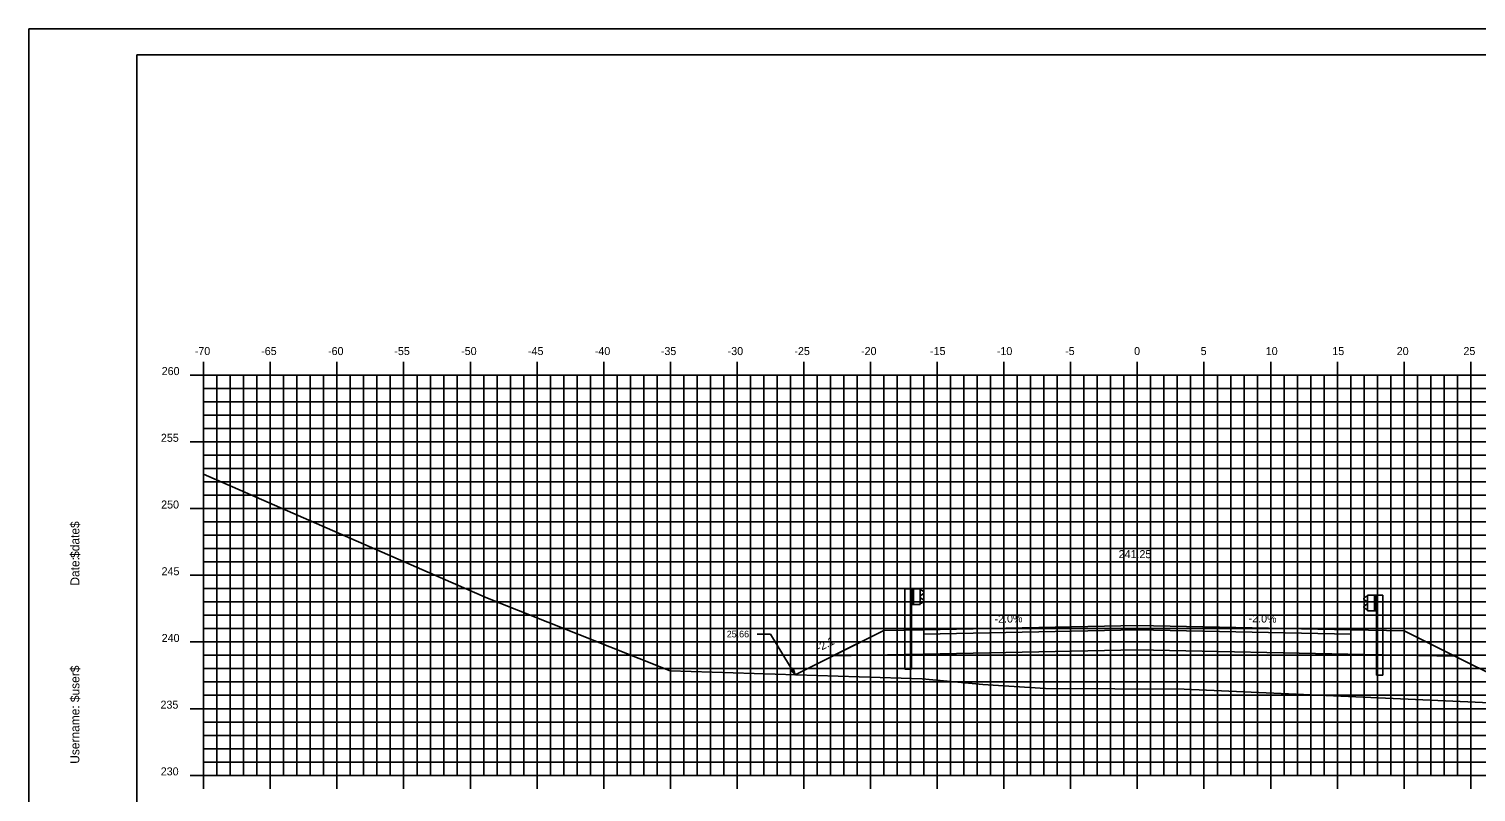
# Model space of a CAD drawing. Extents: x 1160718 to 1173142, y 616002 to 617630.
# Drawn here: x 1169435.8 to 1169544.3, y 616666.7 to 616723.9 of the extents above; entities that cross this region are included whole.
import ezdxf

# ---------------------------------------------------------------- set-up
doc = ezdxf.new("R2010")
doc.units = 0
for name, color, linetype in [('ANNOTATION', 7, 'Continuous'), ('BORDER', 7, 'Continuous'), ('D_Guardrail_Beam_Lt', 7, 'Continuous'), ('D_Guardrail_Beam_Rt', 7, 'Continuous'), ('D_Roadway_Centerline', 7, 'Continuous'), ('D_Roadway_Centerline_Text', 7, 'Continuous'), ('D_Roadway_Edge_Shoulder', 7, 'Continuous'), ('D_Roadway_Edge_TW', 7, 'Continuous'), ('D_Roadway_Pavement', 7, 'Continuous'), ('D_Roadway_SlopeLines', 7, 'Continuous'), ('D_Roadway_SubGrade', 7, 'Continuous'), ('H_V ANNOTATION', 7, 'Continuous'), ('MAJOR', 7, 'Continuous'), ('MINOR', 7, 'Continuous'), ('PLOT BOUNDARY', 7, 'Continuous'), ('S_Roadway_Centerline', 7, 'Continuous')]:
    doc.layers.add(name, color=color, linetype=linetype)

msp = doc.modelspace()

# ---------------------------------------------------------------- linework, layer by layer
at = {"layer": 'ANNOTATION'}
for p in [(1169490.39, 616678.52), (1169493.22, 616675.46)]:
    msp.add_line(p, (1169491.39, 616678.52), dxfattribs=at)
msp.add_lwpolyline([(1169496.06, 616676.89), (1169502.88, 616677.02), (1169518.88, 616677.34), (1169535.88, 616677), (1169542.7, 616676.87)], dxfattribs=at)
msp.add_lwpolyline([(1169493.07, 616675.96), (1169493.22, 616675.46), (1169492.86, 616675.83)], close=True, dxfattribs=at)
at = {"layer": 'BORDER'}
for p, q in [((1169603.88, 616721.93), (1169443.88, 616721.93)), ((1169443.88, 616721.93), (1169443.88, 616616.93))]:
    msp.add_line(p, q, dxfattribs=at)
at = {"layer": 'D_Guardrail_Beam_Lt'}
for p, q in [((1169501.45, 616681.9), (1169501.45, 616675.9)), ((1169501.92, 616681.9), (1169501.45, 616681.9)), ((1169502.61, 616681.9), (1169501.92, 616681.9)), ((1169501.92, 616681.9), (1169501.92, 616680.74)), ((1169501.99, 616681.9), (1169501.99, 616680.74)), ((1169502.09, 616681.9), (1169502.09, 616680.74)), ((1169502.61, 616680.74), (1169502.61, 616681.9)), ((1169502.61, 616681.82), (1169502.68, 616681.8)), ((1169502.61, 616681.35), (1169502.61, 616681.28)), ((1169502.84, 616681.55), (1169502.65, 616681.42)), ((1169502.65, 616681.22), (1169502.84, 616681.08)), ((1169502.7, 616681.8), (1169502.84, 616681.7)), ((1169501.92, 616680.74), (1169502.61, 616680.74)), ((1169501.94, 616675.9), (1169501.94, 616680.74)), ((1169502.68, 616680.83), (1169502.61, 616680.82)), ((1169502.84, 616680.94), (1169502.7, 616680.84)), ((1169501.94, 616675.9), (1169501.45, 616675.9))]:
    msp.add_line(p, q, dxfattribs=at)
for centre, major_axis, start_param, end_param in [((1169502.69, 616681.35), (-0.0789, 0), 5.323254, 6.283185), ((1169502.69, 616681.28), (-0.0789, 0), 6.283185, 7.243116), ((1169502.68, 616681.76), (0.0417, 0), 0.959931, 1.376053), ((1169502.79, 616681.63), (0.0877, 0), 5.323254, 7.243116), ((1169502.68, 616680.87), (0.0417, 0), 4.907132, 5.323254), ((1169502.79, 616681.01), (0.0877, 0), 5.323254, 7.243116)]:
    msp.add_ellipse(centre, major_axis=major_axis, ratio=0.995501, start_param=start_param, end_param=end_param, dxfattribs=at)
at = {"layer": 'D_Guardrail_Beam_Rt'}
for p, q in [((1169536.04, 616681.33), (1169535.9, 616681.23)), ((1169536.13, 616681.36), (1169536.06, 616681.34)), ((1169536.13, 616681.44), (1169536.82, 616681.44)), ((1169536.13, 616680.27), (1169536.13, 616681.44)), ((1169536.65, 616681.44), (1169536.65, 616680.27)), ((1169536.76, 616681.44), (1169536.76, 616680.27)), ((1169536.82, 616681.44), (1169537.29, 616681.44)), ((1169536.82, 616681.44), (1169536.82, 616680.27)), ((1169537.29, 616681.44), (1169537.29, 616675.44)), ((1169535.9, 616681.09), (1169536.09, 616680.95)), ((1169536.09, 616680.76), (1169535.9, 616680.62)), ((1169535.9, 616680.48), (1169536.04, 616680.38)), ((1169536.06, 616680.37), (1169536.13, 616680.36)), ((1169536.13, 616680.89), (1169536.13, 616680.82)), ((1169536.82, 616680.27), (1169536.13, 616680.27)), ((1169536.8, 616675.44), (1169536.8, 616680.27)), ((1169536.8, 616675.44), (1169537.29, 616675.44))]:
    msp.add_line(p, q, dxfattribs=at)
for centre, major_axis, start_param, end_param in [((1169535.95, 616681.16), (-0.0877, 0), 5.323254, 7.243116), ((1169536.07, 616681.3), (-0.0417, 0), 4.907132, 5.323254), ((1169535.95, 616680.55), (-0.0877, 0), 5.323254, 7.243116), ((1169536.07, 616680.41), (-0.0417, 0), 0.959931, 1.376053), ((1169536.05, 616680.89), (0.0789, 0), 0, 0.959931), ((1169536.05, 616680.82), (0.0789, 0), 5.323254, 6.283185)]:
    msp.add_ellipse(centre, major_axis=major_axis, ratio=0.995501, start_param=start_param, end_param=end_param, dxfattribs=at)
at = {"layer": 'D_Roadway_Edge_Shoulder'}
for points in [[(1169502.88, 616678.85), (1169502.88, 616678.52)], [(1169534.88, 616678.85), (1169534.88, 616678.52)]]:
    msp.add_lwpolyline(points, dxfattribs=at)
at = {"layer": 'D_Roadway_Edge_TW'}
msp.add_lwpolyline([(1169502.88, 616678.52), (1169502.88, 616678.85), (1169518.88, 616679.17), (1169534.88, 616678.85), (1169534.88, 616678.52), (1169518.88, 616678.84)], close=True, dxfattribs=at)
at = {"layer": 'D_Roadway_Pavement'}
msp.add_lwpolyline([(1169502.88, 616678.52), (1169502.88, 616678.52), (1169518.88, 616678.84), (1169534.88, 616678.52), (1169534.88, 616678.52), (1169518.88, 616678.84)], close=True, dxfattribs=at)
for points in [[(1169502.88, 616678.52), (1169502.88, 616678.52)], [(1169502.88, 616678.52), (1169502.88, 616678.52)], [(1169534.88, 616678.52), (1169534.88, 616678.52)], [(1169534.88, 616678.52), (1169534.88, 616678.52)]]:
    msp.add_lwpolyline(points, dxfattribs=at)
at = {"layer": 'D_Roadway_SlopeLines'}
for points in [[(1169499.88, 616678.79), (1169493.22, 616675.46)], [(1169538.88, 616678.77), (1169549.91, 616673.26)]]:
    msp.add_lwpolyline(points, dxfattribs=at)
at = {"layer": 'D_Roadway_SubGrade'}
for p, q in [((1169534.88, 616678.85), (1169538.88, 616678.77)), ((1169534.88, 616677.02), (1169534.88, 616678.85)), ((1169538.88, 616678.77), (1169543.74, 616676.34))]:
    msp.add_line(p, q, dxfattribs=at)
for points in [[(1169502.88, 616677.02), (1169502.88, 616678.85), (1169499.88, 616678.79), (1169496.06, 616676.89)], [(1169502.88, 616677.02), (1169502.88, 616678.52), (1169518.88, 616678.84), (1169534.88, 616678.52), (1169534.88, 616677.02)]]:
    msp.add_lwpolyline(points, dxfattribs=at)
at = {"layer": 'MAJOR'}
for p, q in [((1169448.88, 616698.93), (1169448.88, 616697.93)), ((1169453.88, 616698.93), (1169453.88, 616697.93)), ((1169458.88, 616698.93), (1169458.88, 616697.93)), ((1169463.88, 616698.93), (1169463.88, 616697.93)), ((1169468.88, 616698.93), (1169468.88, 616697.93)), ((1169473.88, 616698.93), (1169473.88, 616697.93)), ((1169478.88, 616698.93), (1169478.88, 616697.93)), ((1169483.88, 616698.93), (1169483.88, 616697.93)), ((1169488.88, 616698.93), (1169488.88, 616697.93)), ((1169493.88, 616698.93), (1169493.88, 616697.93)), ((1169498.88, 616698.93), (1169498.88, 616697.93)), ((1169503.88, 616698.93), (1169503.88, 616697.93)), ((1169508.88, 616698.93), (1169508.88, 616697.93)), ((1169513.88, 616698.93), (1169513.88, 616697.93)), ((1169518.88, 616698.93), (1169518.88, 616697.93)), ((1169523.88, 616698.93), (1169523.88, 616697.93)), ((1169528.88, 616698.93), (1169528.88, 616697.93)), ((1169533.88, 616698.93), (1169533.88, 616697.93)), ((1169538.88, 616698.93), (1169538.88, 616697.93)), ((1169543.88, 616698.93), (1169543.88, 616697.93)), ((1169447.88, 616697.93), (1169448.88, 616697.93)), ((1169448.88, 616697.93), (1169588.88, 616697.93)), ((1169448.88, 616667.93), (1169448.88, 616697.93)), ((1169448.88, 616667.93), (1169448.88, 616697.93)), ((1169448.88, 616697.93), (1169588.88, 616697.93)), ((1169453.88, 616667.93), (1169453.88, 616697.93)), ((1169458.88, 616667.93), (1169458.88, 616697.93)), ((1169463.88, 616667.93), (1169463.88, 616697.93)), ((1169468.88, 616667.93), (1169468.88, 616697.93)), ((1169473.88, 616667.93), (1169473.88, 616697.93)), ((1169478.88, 616667.93), (1169478.88, 616697.93)), ((1169483.88, 616667.93), (1169483.88, 616697.93)), ((1169488.88, 616667.93), (1169488.88, 616697.93)), ((1169493.88, 616667.93), (1169493.88, 616697.93)), ((1169498.88, 616667.93), (1169498.88, 616697.93)), ((1169503.88, 616667.93), (1169503.88, 616697.93)), ((1169508.88, 616667.93), (1169508.88, 616697.93)), ((1169513.88, 616667.93), (1169513.88, 616697.93)), ((1169518.88, 616667.93), (1169518.88, 616697.93)), ((1169523.88, 616667.93), (1169523.88, 616697.93)), ((1169528.88, 616667.93), (1169528.88, 616697.93)), ((1169533.88, 616667.93), (1169533.88, 616697.93)), ((1169538.88, 616667.93), (1169538.88, 616697.93)), ((1169543.88, 616667.93), (1169543.88, 616697.93)), ((1169447.88, 616692.93), (1169448.88, 616692.93)), ((1169448.88, 616692.93), (1169588.88, 616692.93)), ((1169447.88, 616687.93), (1169448.88, 616687.93)), ((1169448.88, 616687.93), (1169588.88, 616687.93)), ((1169447.88, 616682.93), (1169448.88, 616682.93)), ((1169448.88, 616682.93), (1169588.88, 616682.93)), ((1169447.88, 616677.93), (1169448.88, 616677.93)), ((1169448.88, 616677.93), (1169588.88, 616677.93)), ((1169447.88, 616672.93), (1169448.88, 616672.93)), ((1169448.88, 616672.93), (1169588.88, 616672.93)), ((1169447.88, 616667.93), (1169448.88, 616667.93)), ((1169448.88, 616667.93), (1169588.88, 616667.93)), ((1169448.88, 616667.93), (1169588.88, 616667.93)), ((1169448.88, 616666.93), (1169448.88, 616667.93)), ((1169453.88, 616666.93), (1169453.88, 616667.93)), ((1169458.88, 616666.93), (1169458.88, 616667.93)), ((1169463.88, 616666.93), (1169463.88, 616667.93)), ((1169468.88, 616666.93), (1169468.88, 616667.93)), ((1169473.88, 616666.93), (1169473.88, 616667.93)), ((1169478.88, 616666.93), (1169478.88, 616667.93)), ((1169483.88, 616666.93), (1169483.88, 616667.93)), ((1169488.88, 616666.93), (1169488.88, 616667.93)), ((1169493.88, 616666.93), (1169493.88, 616667.93)), ((1169498.88, 616666.93), (1169498.88, 616667.93)), ((1169503.88, 616666.93), (1169503.88, 616667.93)), ((1169508.88, 616666.93), (1169508.88, 616667.93)), ((1169513.88, 616666.93), (1169513.88, 616667.93)), ((1169518.88, 616666.93), (1169518.88, 616667.93)), ((1169523.88, 616666.93), (1169523.88, 616667.93)), ((1169528.88, 616666.93), (1169528.88, 616667.93)), ((1169533.88, 616666.93), (1169533.88, 616667.93)), ((1169538.88, 616666.93), (1169538.88, 616667.93)), ((1169543.88, 616666.93), (1169543.88, 616667.93))]:
    msp.add_line(p, q, dxfattribs=at)
at = {"layer": 'MINOR'}
for p, q in [((1169449.88, 616667.93), (1169449.88, 616697.93)), ((1169450.88, 616667.93), (1169450.88, 616697.93)), ((1169451.88, 616667.93), (1169451.88, 616697.93)), ((1169452.88, 616667.93), (1169452.88, 616697.93)), ((1169454.88, 616667.93), (1169454.88, 616697.93)), ((1169455.88, 616667.93), (1169455.88, 616697.93)), ((1169456.88, 616667.93), (1169456.88, 616697.93)), ((1169457.88, 616667.93), (1169457.88, 616697.93)), ((1169459.88, 616667.93), (1169459.88, 616697.93)), ((1169460.88, 616667.93), (1169460.88, 616697.93)), ((1169461.88, 616667.93), (1169461.88, 616697.93)), ((1169462.88, 616667.93), (1169462.88, 616697.93)), ((1169464.88, 616667.93), (1169464.88, 616697.93)), ((1169465.88, 616667.93), (1169465.88, 616697.93)), ((1169466.88, 616667.93), (1169466.88, 616697.93)), ((1169467.88, 616667.93), (1169467.88, 616697.93)), ((1169469.88, 616667.93), (1169469.88, 616697.93)), ((1169470.88, 616667.93), (1169470.88, 616697.93)), ((1169471.88, 616667.93), (1169471.88, 616697.93)), ((1169472.88, 616667.93), (1169472.88, 616697.93)), ((1169474.88, 616667.93), (1169474.88, 616697.93)), ((1169475.88, 616667.93), (1169475.88, 616697.93)), ((1169476.88, 616667.93), (1169476.88, 616697.93)), ((1169477.88, 616667.93), (1169477.88, 616697.93)), ((1169479.88, 616667.93), (1169479.88, 616697.93)), ((1169480.88, 616667.93), (1169480.88, 616697.93)), ((1169481.88, 616667.93), (1169481.88, 616697.93)), ((1169482.88, 616667.93), (1169482.88, 616697.93)), ((1169484.88, 616667.93), (1169484.88, 616697.93)), ((1169485.88, 616667.93), (1169485.88, 616697.93)), ((1169486.88, 616667.93), (1169486.88, 616697.93)), ((1169487.88, 616667.93), (1169487.88, 616697.93)), ((1169489.88, 616667.93), (1169489.88, 616697.93)), ((1169490.88, 616667.93), (1169490.88, 616697.93)), ((1169491.88, 616667.93), (1169491.88, 616697.93)), ((1169492.88, 616667.93), (1169492.88, 616697.93)), ((1169494.88, 616667.93), (1169494.88, 616697.93)), ((1169495.88, 616667.93), (1169495.88, 616697.93)), ((1169496.88, 616667.93), (1169496.88, 616697.93)), ((1169497.88, 616667.93), (1169497.88, 616697.93)), ((1169499.88, 616667.93), (1169499.88, 616697.93)), ((1169500.88, 616667.93), (1169500.88, 616697.93)), ((1169501.88, 616667.93), (1169501.88, 616697.93)), ((1169502.88, 616667.93), (1169502.88, 616697.93)), ((1169504.88, 616667.93), (1169504.88, 616697.93)), ((1169505.88, 616667.93), (1169505.88, 616697.93)), ((1169506.88, 616667.93), (1169506.88, 616697.93)), ((1169507.88, 616667.93), (1169507.88, 616697.93)), ((1169509.88, 616667.93), (1169509.88, 616697.93)), ((1169510.88, 616667.93), (1169510.88, 616697.93)), ((1169511.88, 616667.93), (1169511.88, 616697.93)), ((1169512.88, 616667.93), (1169512.88, 616697.93)), ((1169514.88, 616667.93), (1169514.88, 616697.93)), ((1169515.88, 616667.93), (1169515.88, 616697.93)), ((1169516.88, 616667.93), (1169516.88, 616697.93)), ((1169517.88, 616667.93), (1169517.88, 616697.93)), ((1169519.88, 616667.93), (1169519.88, 616697.93)), ((1169520.88, 616667.93), (1169520.88, 616697.93)), ((1169521.88, 616667.93), (1169521.88, 616697.93)), ((1169522.88, 616667.93), (1169522.88, 616697.93)), ((1169524.88, 616667.93), (1169524.88, 616697.93)), ((1169525.88, 616667.93), (1169525.88, 616697.93)), ((1169526.88, 616667.93), (1169526.88, 616697.93)), ((1169527.88, 616667.93), (1169527.88, 616697.93)), ((1169529.88, 616667.93), (1169529.88, 616697.93)), ((1169530.88, 616667.93), (1169530.88, 616697.93)), ((1169531.88, 616667.93), (1169531.88, 616697.93)), ((1169532.88, 616667.93), (1169532.88, 616697.93)), ((1169534.88, 616667.93), (1169534.88, 616697.93)), ((1169535.88, 616667.93), (1169535.88, 616697.93)), ((1169536.88, 616667.93), (1169536.88, 616697.93)), ((1169537.88, 616667.93), (1169537.88, 616697.93)), ((1169539.88, 616667.93), (1169539.88, 616697.93)), ((1169540.88, 616667.93), (1169540.88, 616697.93)), ((1169541.88, 616667.93), (1169541.88, 616697.93)), ((1169542.88, 616667.93), (1169542.88, 616697.93)), ((1169448.88, 616696.93), (1169588.88, 616696.93)), ((1169448.88, 616696.93), (1169449.88, 616696.93)), ((1169448.88, 616695.93), (1169588.88, 616695.93)), ((1169448.88, 616695.93), (1169449.88, 616695.93)), ((1169448.88, 616694.93), (1169588.88, 616694.93)), ((1169448.88, 616694.93), (1169449.88, 616694.93)), ((1169448.88, 616693.93), (1169588.88, 616693.93)), ((1169448.88, 616693.93), (1169449.88, 616693.93)), ((1169448.88, 616691.93), (1169588.88, 616691.93)), ((1169448.88, 616691.93), (1169449.88, 616691.93)), ((1169448.88, 616690.93), (1169588.88, 616690.93)), ((1169448.88, 616690.93), (1169449.88, 616690.93)), ((1169448.88, 616689.93), (1169588.88, 616689.93)), ((1169448.88, 616689.93), (1169449.88, 616689.93)), ((1169448.88, 616688.93), (1169588.88, 616688.93)), ((1169448.88, 616688.93), (1169449.88, 616688.93)), ((1169448.88, 616686.93), (1169588.88, 616686.93)), ((1169448.88, 616686.93), (1169449.88, 616686.93)), ((1169448.88, 616685.93), (1169588.88, 616685.93)), ((1169448.88, 616685.93), (1169449.88, 616685.93)), ((1169448.88, 616684.93), (1169588.88, 616684.93)), ((1169448.88, 616684.93), (1169449.88, 616684.93)), ((1169448.88, 616683.93), (1169588.88, 616683.93)), ((1169448.88, 616683.93), (1169449.88, 616683.93)), ((1169448.88, 616681.93), (1169588.88, 616681.93)), ((1169448.88, 616681.93), (1169449.88, 616681.93)), ((1169448.88, 616680.93), (1169588.88, 616680.93)), ((1169448.88, 616680.93), (1169449.88, 616680.93)), ((1169448.88, 616679.93), (1169588.88, 616679.93)), ((1169448.88, 616679.93), (1169449.88, 616679.93)), ((1169448.88, 616678.93), (1169588.88, 616678.93)), ((1169448.88, 616678.93), (1169449.88, 616678.93)), ((1169448.88, 616676.93), (1169588.88, 616676.93)), ((1169448.88, 616676.93), (1169449.88, 616676.93)), ((1169448.88, 616675.93), (1169588.88, 616675.93)), ((1169448.88, 616675.93), (1169449.88, 616675.93)), ((1169448.88, 616674.93), (1169588.88, 616674.93)), ((1169448.88, 616674.93), (1169449.88, 616674.93)), ((1169448.88, 616673.93), (1169588.88, 616673.93)), ((1169448.88, 616673.93), (1169449.88, 616673.93)), ((1169448.88, 616671.93), (1169588.88, 616671.93)), ((1169448.88, 616671.93), (1169449.88, 616671.93)), ((1169448.88, 616670.93), (1169588.88, 616670.93)), ((1169448.88, 616670.93), (1169449.88, 616670.93)), ((1169448.88, 616669.93), (1169588.88, 616669.93)), ((1169448.88, 616669.93), (1169449.88, 616669.93)), ((1169448.88, 616668.93), (1169588.88, 616668.93)), ((1169448.88, 616668.93), (1169449.88, 616668.93))]:
    msp.add_line(p, q, dxfattribs=at)
at = {"layer": 'PLOT BOUNDARY'}
msp.add_lwpolyline([(1169435.79, 616613.87), (1169605.79, 616613.87), (1169605.79, 616723.87), (1169435.79, 616723.87)], close=True, dxfattribs=at)
at = {"layer": 'S_Roadway_Centerline'}
msp.add_lwpolyline([(1169448.88, 616690.5), (1169470.17, 616681.22), (1169483.86, 616675.77), (1169502.74, 616675.16), (1169507.29, 616674.75), (1169511.99, 616674.43), (1169522.4, 616674.4), (1169547.02, 616673.29), (1169568.23, 616673.19), (1169584.32, 616679.82), (1169588.88, 616681.72)], dxfattribs=at)

# ---------------------------------------------------------------- texts
at = {"layer": 'ANNOTATION'}
for s, rotation, p in [('-2.0%', 1.1458, (1169508.18, 616679.36)), ('-2.0%', 358.8542, (1169527.22, 616679.41)), ('-2:1', 26.5651, (1169495, 616677.18))]:
    msp.add_text(s, height=0.6, rotation=rotation, dxfattribs=at).set_placement(p)
msp.add_text("25.66'", height=0.5, dxfattribs=at).set_placement((1169488.1, 616678.27))
at = {"layer": 'BORDER'}
for s, p in [('$date$', (1169439.57, 616684.23)), ('Date:', (1169439.57, 616682.15)), ('$user$', (1169439.57, 616673.42)), ('Username:', (1169439.57, 616668.8))]:
    msp.add_text(s, height=0.67, rotation=90, dxfattribs=at).set_placement(p)
at = {"layer": 'D_Roadway_Centerline'}
for s in ['C', 'L']:
    msp.add_text(s, height=0.0146, dxfattribs=at).set_placement((1169518.88, 616679.17))
at = {"layer": 'D_Roadway_Centerline_Text'}
msp.add_text('241.25', height=0.6, dxfattribs=at).set_placement((1169517.48, 616684.21))
at = {"layer": 'H_V ANNOTATION'}
for s, p in [('-70', (1169448.22, 616699.43)), ('-65', (1169453.2, 616699.43)), ('-60', (1169458.21, 616699.43)), ('-55', (1169463.18, 616699.43)), ('-50', (1169468.19, 616699.43)), ('-45', (1169473.2, 616699.43)), ('-40', (1169478.21, 616699.43)), ('-35', (1169483.16, 616699.43)), ('-30', (1169488.17, 616699.43)), ('-25', (1169493.17, 616699.43)), ('-20', (1169498.17, 616699.43)), ('-15', (1169503.34, 616699.43)), ('-10', (1169508.35, 616699.43)), ('-5', (1169513.47, 616699.43)), ('0', (1169518.64, 616699.43)), ('5', (1169523.63, 616699.43)), ('10', (1169528.51, 616699.43)), ('15', (1169533.5, 616699.43)), ('20', (1169538.33, 616699.43)), ('25', (1169543.33, 616699.43)), ('260', (1169445.74, 616697.93)), ('255', (1169445.68, 616692.93)), ('250', (1169445.7, 616687.93)), ('245', (1169445.73, 616682.93)), ('240', (1169445.74, 616677.93)), ('235', (1169445.65, 616672.93)), ('230', (1169445.67, 616667.93))]:
    msp.add_text(s, height=0.6, dxfattribs=at).set_placement(p)

doc.saveas('drawing.dxf')
